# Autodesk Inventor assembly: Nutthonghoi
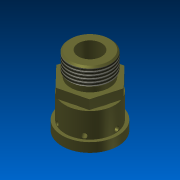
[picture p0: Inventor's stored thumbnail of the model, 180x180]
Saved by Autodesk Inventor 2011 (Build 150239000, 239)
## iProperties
Created: 2011-04
Part Number: Nutthonghoi
Document SubType Name: Assembly
Designer: 904Chiaki
Author: 904Chiaki
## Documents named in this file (3)
- E:\2.FINISH\DOAN_CTM_final\Nutthonghoi.iam
- E:\2.FINISH\DOAN_CTM_final\Daunut.ipt
- E:\2.FINISH\DOAN_CTM_final\Thannut.ipt
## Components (2 placed, 2 different names)
1. Daunut:1 — Mate:1, Mate:2, Mate:4
2. Thannut:1 — Mate:1, Mate:2, Mate:3
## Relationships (4: Mate 4)
- Mate:1: Daunut:1 ↔ Thannut:1
- Mate:2: Daunut:1 ↔ Thannut:1
- Mate:3: Thannut:1
- Mate:4: Daunut:1
